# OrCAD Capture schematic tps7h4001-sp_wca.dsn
size C
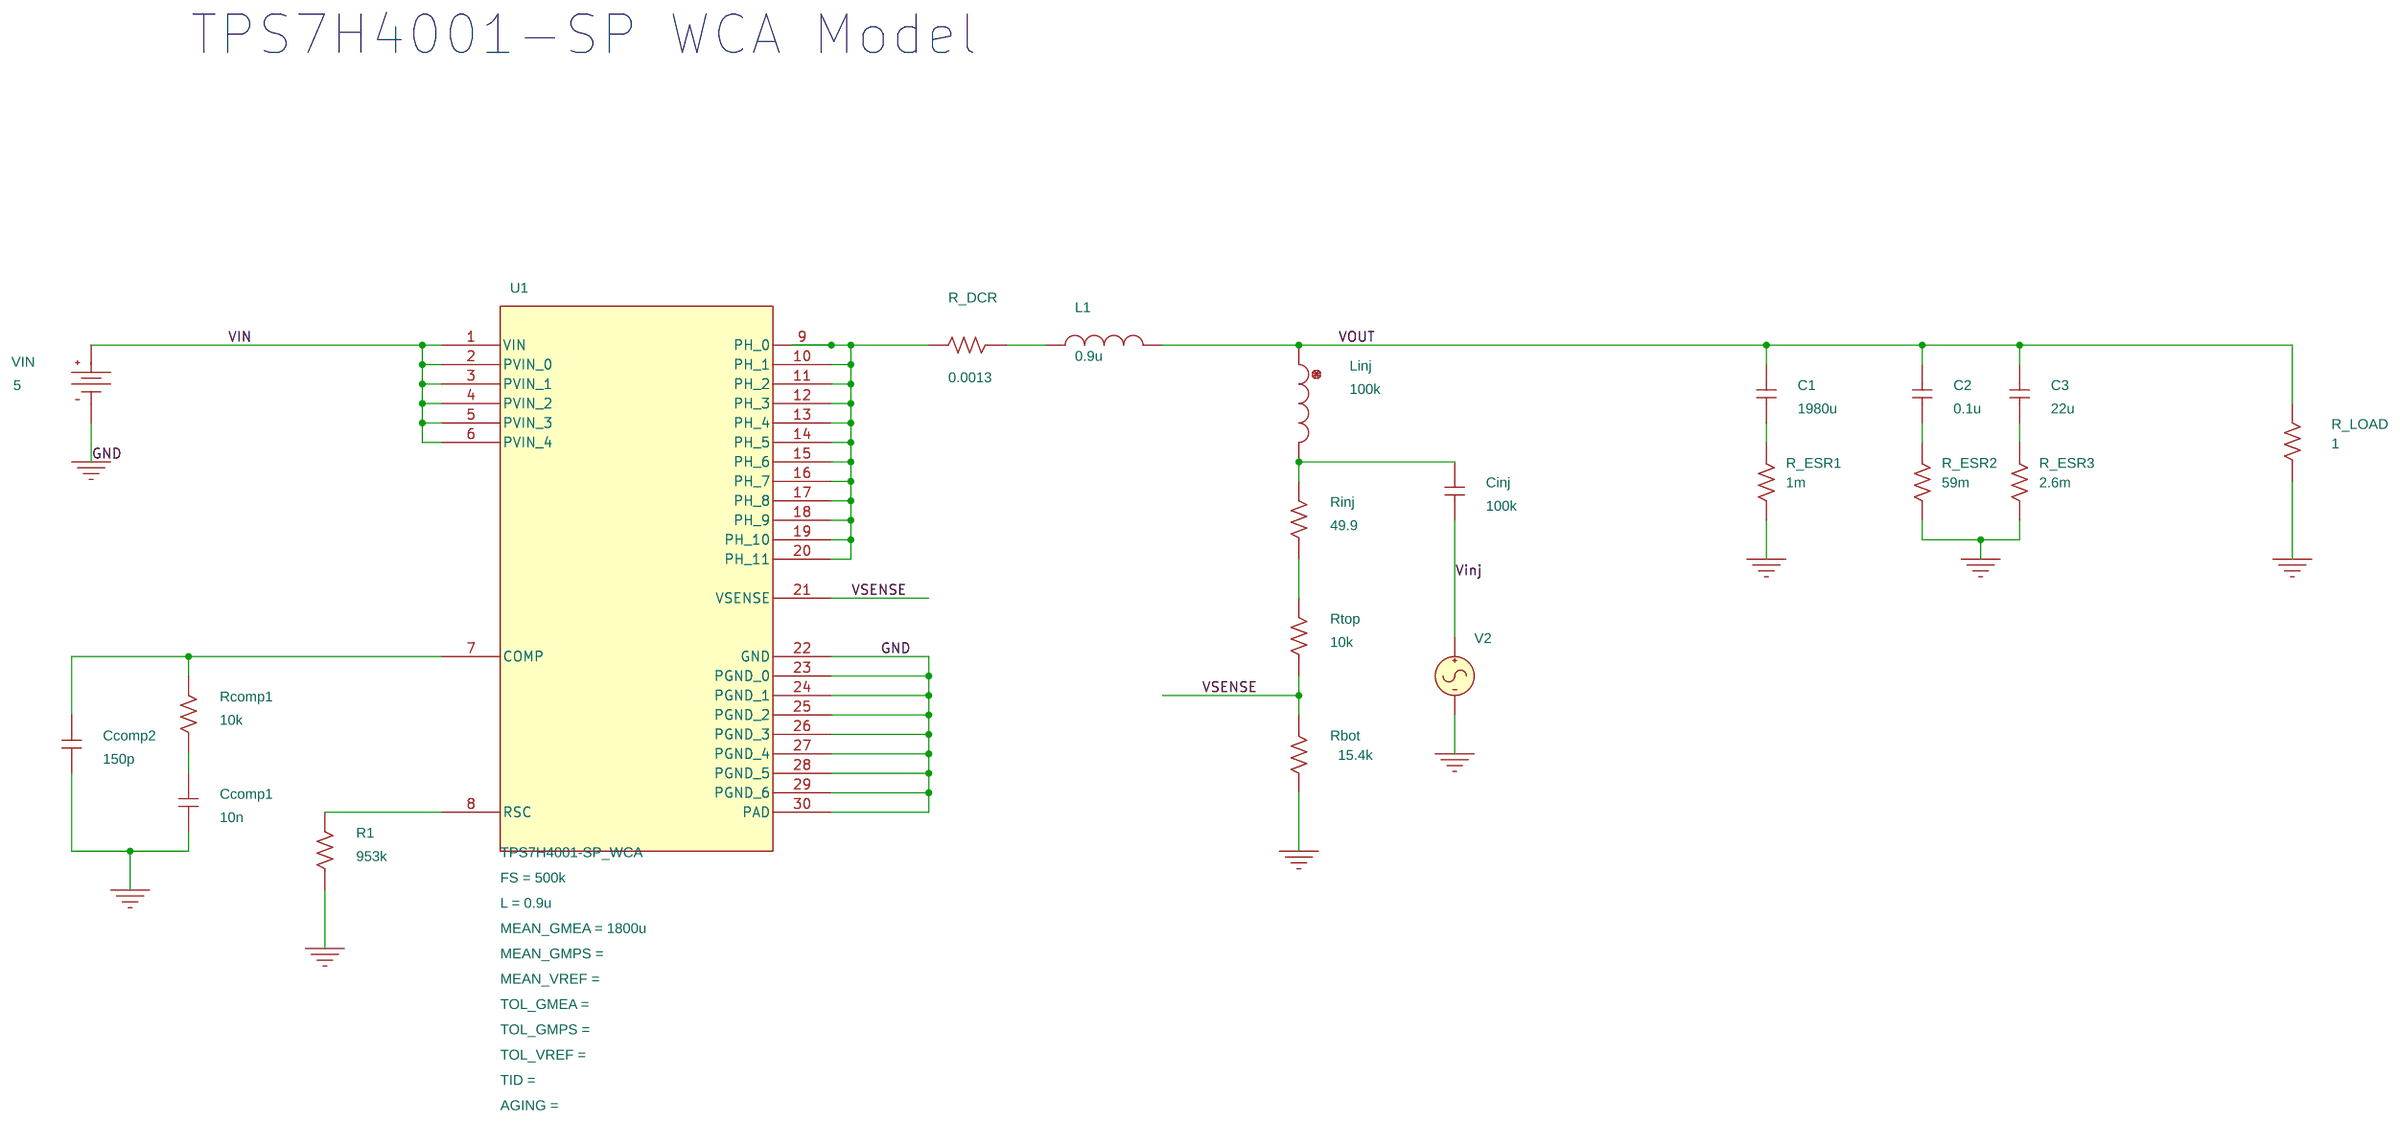
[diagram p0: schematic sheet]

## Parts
C1  1980u  [RAD/CK05]
C2  0.1u  [RAD/CK05]
C3  22u  [RAD/CK05]
Ccomp1  10n  [RAD/CK05]
Ccomp2  150p  [RAD/CK05]
Cinj  100k  [RAD/CK05]
L1  0.9u  [DISC/.350x.175/LS.200x.100/.034]
Linj  100k  [DISC/.350x.175/LS.200x.100/.034]
R1  953k  [AX/RC05]
R_DCR  0.0013  [AX/RC05]
R_ESR1  1m  [AX/RC05]
R_ESR2  59m  [AX/RC05]
R_ESR3  2.6m  [AX/RC05]
R_LOAD  1  [AX/RC05]
Rbot  15.4k  [AX/RC05]
Rcomp1  10k  [AX/RC05]
Rinj  49.9  [AX/RC05]
Rtop  10k  [AX/RC05]
U1  TPS7H4001-SP_WCA
V2  VAC
VIN  VDC

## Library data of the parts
C1-C3 Ccomp1 Ccomp2 Cinj = C
L1 = L_v2
Linj = L
R1 R_DCR R_ESR1-R_ESR3 R_LOAD Rbot Rcomp1 Rinj Rtop = R
U1 = TPS7H4001-SP_WCA_2: FS: 500k; L: 0.9u; MEAN_GMEA: 1800u; PSpiceTemplate: X^@REFDES  %VIN %PVIN_0 %PVIN_1 %PVIN_2 %PVIN_3 %PVIN_4 %COMP %RSC %PH_0 %PH_1 %PH_2 %PH_3 %PH_4 %PH_5 %PH_6 %PH_7 %PH_8 %PH_9 %PH_10 %PH_11 %VSENSE %GND %PGND_0 %PGND_1 %PGND_2 %PGND_3 %PGND_4 %PGND_5 %PGND_6 %PAD @MODEL PARAMS: ?AGING|AGING=@AGING||AGING=0| ?FS|FS=@FS||FS=500k| ?L|L=@L||L=0.9u| ?Mean_GMea|Mean_GMea=@Mean_GMea||Mean_GMea=1800u| ?Mean_GMps|Mean_GMps=@Mean_GMps||Mean_GMps=40| ?Mean_Vref|Mean_Vref=@Mean_Vref||Mean_Vref=0.605| ?TID|TID=@TID||TID=0| ?Tol_GMea|Tol_GMea=@Tol_GMea||Tol_GMea=0.0872| ?Tol_GMps|Tol_GMps=@Tol_GMps||Tol_GMps=0.0522| ?Tol_Vref|Tol_Vref=@Tol_Vref||Tol_Vref=0.0031|
V2 = VAC
VIN = VDC: DC: 5

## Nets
VIN: U1.1(VIN) U1.2(PVIN_0) U1.3(PVIN_1) U1.4(PVIN_2) U1.5(PVIN_3) U1.6(PVIN_4) VIN.0(+)
Vinj: Cinj.2 V2.1(+)
0: Ccomp1.2 Ccomp2.2 R1.1 R_ESR1.2 R_ESR2.2 R_ESR3.2 R_LOAD.1 Rbot.2 U1.22(GND) U1.23(PGND_0) U1.24(PGND_1) U1.25(PGND_2) U1.26(PGND_3) U1.27(PGND_4) U1.28(PGND_5) U1.29(PGND_6) U1.30(PAD) V2.2(-) VIN.1(-)
VOUT: C1.1 C2.1 C3.1 L1.2 Linj.1 R_LOAD.2
VSENSE: Rbot.1 Rtop.1 U1.21(VSENSE)
N16777895: Ccomp2.1 Rcomp1.2 U1.7(COMP)
N16777925: Ccomp1.1 Rcomp1.1
N16778023: R1.2 U1.8(RSC)
N16778717: R_DCR.2 U1.9(PH_0) U1.10(PH_1) U1.11(PH_2) U1.12(PH_3) U1.13(PH_4) U1.14(PH_5) U1.15(PH_6) U1.16(PH_7) U1.17(PH_8) U1.18(PH_9) U1.19(PH_10) U1.20(PH_11)
N16778720: L1.1 R_DCR.1
N16778778: C1.2 R_ESR1.1
N16778781: C2.2 R_ESR2.1
N16778784: C3.2 R_ESR3.1
N16778798: Cinj.1 Linj.2 Rinj.2
N16778876: Rinj.1 Rtop.2

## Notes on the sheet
- TPS7H4001-SP WCA Model
